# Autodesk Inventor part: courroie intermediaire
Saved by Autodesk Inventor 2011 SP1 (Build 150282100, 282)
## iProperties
Created: 2010-12
Part Number: courroie intermediaire
Document SubType Name: Modeling
Designer: eric
Density: 1 g/cm^3
Author: eric
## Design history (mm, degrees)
feature "Base1"
node "Solide1"
node "Corps solides"
node "Corps surfaciques"
